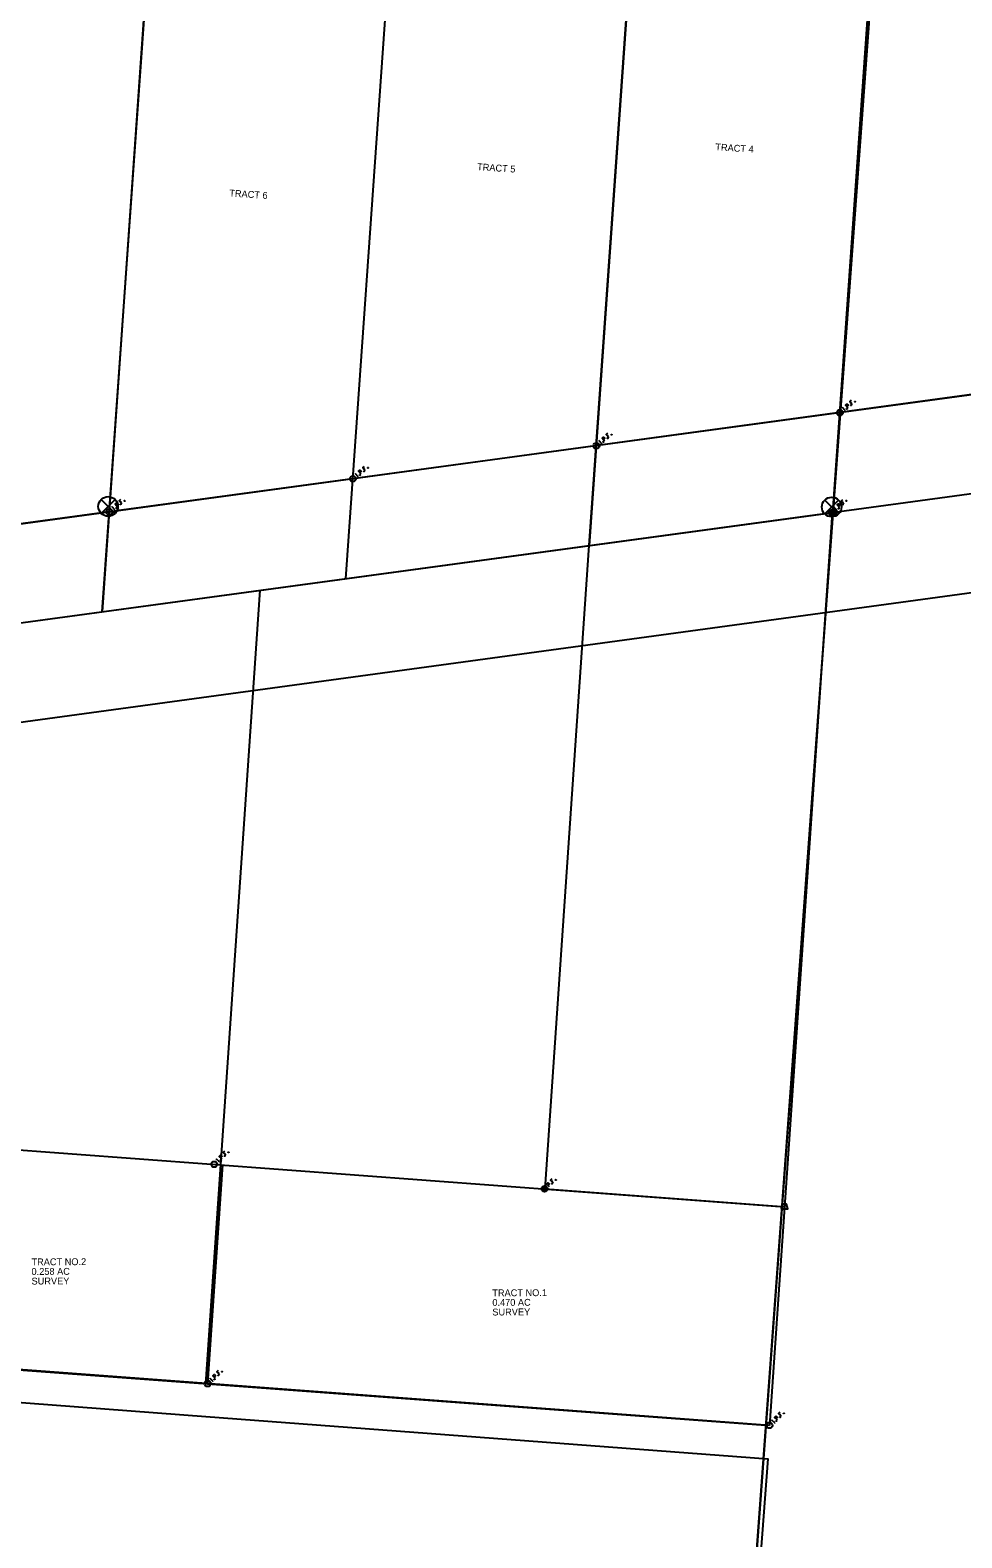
# Model space of a CAD drawing. Extents: x 1532954 to 1577849, y 698998 to 706606.
# Drawn here: x 1574206 to 1574585, y 702823 to 703437 of the extents above; entities that cross this region are included whole.
import ezdxf

# ---------------------------------------------------------------- set-up
doc = ezdxf.new("R2010")
doc.units = 0
for name, color, linetype in [('Default', 7, 'Continuous'), ('DV_X_Property_Line', 7, 'Continuous'), ('GM_X_Major_Lake_Text', 7, 'Continuous'), ('RW_X_Esmt_SH', 7, 'Continuous'), ('SC_Scratch1', 7, 'Continuous'), ('SC_Scratch10', 7, 'Continuous'), ('SC_Scratch3', 7, 'Continuous')]:
    doc.layers.add(name, color=color, linetype=linetype)

msp = doc.modelspace()

# ---------------------------------------------------------------- linework, layer by layer
at = {"layer": 'Default'}
for p, q in [((1574235.11, 703245.67), (1574240.77, 703240.01)), ((1574235.11, 703240.01), (1574240.77, 703245.67)), ((1574237.94, 703242.84), (1574237.94, 703242.84)), ((1574529.51, 703245.46), (1574535.17, 703239.8)), ((1574529.51, 703239.8), (1574535.17, 703245.46)), ((1574532.34, 703242.63), (1574532.34, 703242.63))]:
    msp.add_line(p, q, dxfattribs=at)
for centre in [(1574237.94, 703242.84), (1574532.34, 703242.63)]:
    msp.add_circle(centre, 4, dxfattribs=at)
at = {"layer": 'DV_X_Property_Line'}
for p, q in [((1574433.73, 703226.99), (1574485.27, 703963.13)), ((1574235.57, 703199.97), (1574287.2, 703937.42)), ((1574415.71, 702964.97), (1574433.63, 703226.97)), ((1574277.71, 702885.59), (1574299.81, 703208.73)), ((1574415.71, 702964.97), (1574511.92, 702957.84)), ((1574152.51, 702894.98), (1574505.39, 702868.85))]:
    msp.add_line(p, q, dxfattribs=at)
at = {"layer": 'GM_X_Major_Lake_Text'}
msp.add_line((1574284.68, 699857.31), (1574764.71, 706396.92), dxfattribs=at)
at = {"layer": 'RW_X_Esmt_SH'}
for p, q in [((1574050.43, 703215.11), (1574859.76, 703325.41)), ((1571959, 702849.32), (1574870.56, 703246.15))]:
    msp.add_line(p, q, dxfattribs=at)
at = {"layer": 'SC_Scratch1'}
msp.add_lwpolyline([(1573381.77, 703087.06), (1573407.03, 703090.53), (1573503.76, 703103.79), (1573600.48, 703117.05), (1573696.98, 703130.28), (1573793.21, 703143.47), (1573818.48, 703146.94), (1573843.76, 703150.4), (1573940.5, 703163.67), (1574012.63, 703173.56), (1574009.55, 703132.76), (1573992.57, 702907.55), (1573992.57, 702907.55), (1574153.57, 702895.41), (1574152.55, 702881.84), (1574277.72, 702872.4), (1574506.31, 702855.16), (1574480.3, 702510.33), (1574373.41, 701092.97)], dxfattribs=at)
at = {"layer": 'SC_Scratch10'}
for p, q in [((1571190.11, 702825.26), (1574958.12, 703338.82)), ((1571190.11, 702825.26), (1574958.12, 703338.82)), ((1571190.11, 702825.26), (1574958.12, 703338.82)), ((1571195.51, 702785.63), (1574963.52, 703299.19)), ((1571200.91, 702745.99), (1574968.92, 703259.55))]:
    msp.add_line(p, q, dxfattribs=at)
at = {"layer": 'SC_Scratch3'}
for p, q in [((1574532.83, 703240.28), (1574584.89, 703979.3)), ((1574433.74, 703226.81), (1574485.8, 703965.84)), ((1574334.65, 703213.35), (1574386.71, 703952.38)), ((1574235.56, 703199.89), (1574287.62, 703938.91)), ((1574832.97, 703321.42), (1574040.25, 703213.72)), ((1574830.1, 703280.66), (1574037.38, 703172.96)), ((1574533.04, 703241.39), (1574533.02, 703240.79)), ((1574533, 703240.3), (1572963.42, 703027.05)), ((1574532.5, 703240.23), (1574172.81, 703191.36)), ((1574325.4, 700421.81), (1574533, 703240.3)), ((1574532.5, 703240.23), (1574507.06, 702868.72)), ((1574159.05, 702984.08), (1574513.15, 702957.75)), ((1574278.46, 702885.72), (1574284.56, 702974.75)), ((1574513.15, 702958.85), (1574513.15, 702958.25)), ((1574507.06, 702868.72), (1574153.25, 702895.02))]:
    msp.add_line(p, q, dxfattribs=at)
for points in [[(1574539.05, 703282.91), (1574538, 703284.11), (1574538.39, 703284.46), (1574538.44, 703284.49), (1574538.52, 703284.52), (1574538.56, 703284.52), (1574538.6, 703284.52), (1574538.68, 703284.51), (1574538.74, 703284.48), (1574538.83, 703284.42), (1574538.93, 703284.3), (1574538.95, 703284.26), (1574538.98, 703284.19), (1574539.01, 703284.09), (1574539, 703284.04), (1574538.99, 703283.99), (1574538.97, 703283.94), (1574538.91, 703283.87), (1574538.51, 703283.52)], [(1574540.26, 703286.09), (1574539.69, 703285.59), (1574540.74, 703284.39)], [(1574540.15, 703284.15), (1574540.19, 703284.19), (1574540.23, 703284.19), (1574540.29, 703284.17), (1574540.33, 703284.13), (1574540.34, 703284.07), (1574540.33, 703284.03), (1574540.29, 703283.99), (1574540.24, 703283.99), (1574540.19, 703284), (1574540.15, 703284.05), (1574540.14, 703284.11), (1574540.15, 703284.15)], [(1574540.2, 703285.01), (1574540.61, 703285.36)], [(1574541.76, 703285.57), (1574541.8, 703285.6), (1574541.84, 703285.61), (1574541.9, 703285.59), (1574541.94, 703285.54), (1574541.95, 703285.48), (1574541.94, 703285.44), (1574541.9, 703285.41), (1574541.86, 703285.4), (1574541.8, 703285.42), (1574541.76, 703285.47), (1574541.75, 703285.53), (1574541.76, 703285.57)], [(1574536.69, 703282.96), (1574536.95, 703283.19)], [(1574537.87, 703281.88), (1574536.82, 703283.08)], [(1574537.74, 703281.76), (1574538.01, 703281.99)], [(1574538.45, 703282.67), (1574538.5, 703282.7), (1574538.54, 703282.71), (1574538.6, 703282.69), (1574538.64, 703282.64), (1574538.65, 703282.58), (1574538.64, 703282.54), (1574538.6, 703282.51), (1574538.55, 703282.5), (1574538.5, 703282.52), (1574538.45, 703282.57), (1574538.45, 703282.63), (1574538.45, 703282.67)], [(1574441.17, 703272.63), (1574440.6, 703272.13), (1574441.65, 703270.93)], [(1574441.11, 703271.54), (1574441.52, 703271.9)], [(1574442.67, 703272.1), (1574442.71, 703272.14), (1574442.75, 703272.14), (1574442.81, 703272.13), (1574442.85, 703272.08), (1574442.86, 703272.02), (1574442.85, 703271.98), (1574442.81, 703271.94), (1574442.77, 703271.94), (1574442.71, 703271.96), (1574442.67, 703272), (1574442.66, 703272.06), (1574442.67, 703272.1)], [(1574437.6, 703269.5), (1574437.86, 703269.73)], [(1574438.78, 703268.41), (1574437.73, 703269.62)], [(1574438.65, 703268.3), (1574438.92, 703268.53)], [(1574439.96, 703269.44), (1574438.91, 703270.65), (1574439.3, 703271), (1574439.35, 703271.02), (1574439.43, 703271.05), (1574439.47, 703271.06), (1574439.51, 703271.06), (1574439.59, 703271.04), (1574439.65, 703271.02), (1574439.74, 703270.96), (1574439.84, 703270.84), (1574439.86, 703270.8), (1574439.89, 703270.73), (1574439.92, 703270.63), (1574439.91, 703270.57), (1574439.9, 703270.53), (1574439.88, 703270.48), (1574439.82, 703270.41), (1574439.42, 703270.06)], [(1574439.36, 703269.21), (1574439.41, 703269.24), (1574439.45, 703269.24), (1574439.51, 703269.23), (1574439.55, 703269.18), (1574439.56, 703269.12), (1574439.55, 703269.08), (1574439.51, 703269.04), (1574439.46, 703269.04), (1574439.41, 703269.06), (1574439.36, 703269.11), (1574439.36, 703269.16), (1574439.36, 703269.21)], [(1574441.06, 703270.69), (1574441.1, 703270.72), (1574441.14, 703270.73), (1574441.2, 703270.71), (1574441.24, 703270.66), (1574441.25, 703270.6), (1574441.24, 703270.56), (1574441.2, 703270.53), (1574441.16, 703270.52), (1574441.1, 703270.54), (1574441.06, 703270.59), (1574441.05, 703270.65), (1574441.06, 703270.69)], [(1574338.51, 703256.04), (1574338.77, 703256.27)], [(1574339.7, 703254.95), (1574338.64, 703256.15)], [(1574339.56, 703254.83), (1574339.83, 703255.07)], [(1574340.87, 703255.98), (1574339.82, 703257.18), (1574340.22, 703257.53), (1574340.27, 703257.56), (1574340.34, 703257.59), (1574340.38, 703257.59), (1574340.42, 703257.6), (1574340.5, 703257.58), (1574340.56, 703257.55), (1574340.65, 703257.49), (1574340.75, 703257.38), (1574340.77, 703257.33), (1574340.8, 703257.26), (1574340.83, 703257.17), (1574340.82, 703257.11), (1574340.81, 703257.07), (1574340.79, 703257.01), (1574340.73, 703256.95), (1574340.33, 703256.6)], [(1574340.27, 703255.74), (1574340.32, 703255.78), (1574340.36, 703255.78), (1574340.42, 703255.77), (1574340.46, 703255.72), (1574340.47, 703255.66), (1574340.46, 703255.62), (1574340.42, 703255.58), (1574340.37, 703255.58), (1574340.32, 703255.59), (1574340.27, 703255.64), (1574340.27, 703255.7), (1574340.27, 703255.74)], [(1574342.08, 703259.17), (1574341.51, 703258.67), (1574342.56, 703257.46)], [(1574341.97, 703257.22), (1574342.01, 703257.26), (1574342.05, 703257.26), (1574342.11, 703257.25), (1574342.15, 703257.2), (1574342.16, 703257.14), (1574342.15, 703257.1), (1574342.11, 703257.06), (1574342.07, 703257.06), (1574342.01, 703257.08), (1574341.97, 703257.12), (1574341.96, 703257.18), (1574341.97, 703257.22)], [(1574342.02, 703258.08), (1574342.43, 703258.44)], [(1574343.58, 703258.64), (1574343.62, 703258.68), (1574343.67, 703258.68), (1574343.72, 703258.66), (1574343.76, 703258.62), (1574343.77, 703258.56), (1574343.76, 703258.52), (1574343.72, 703258.48), (1574343.68, 703258.48), (1574343.62, 703258.49), (1574343.58, 703258.54), (1574343.57, 703258.6), (1574343.58, 703258.64)], [(1574239.42, 703242.57), (1574239.68, 703242.81)], [(1574240.61, 703241.49), (1574239.55, 703242.69)], [(1574240.47, 703241.37), (1574240.74, 703241.6)], [(1574241.78, 703242.52), (1574240.73, 703243.72), (1574241.13, 703244.07), (1574241.18, 703244.1), (1574241.25, 703244.13), (1574241.29, 703244.13), (1574241.33, 703244.13), (1574241.41, 703244.12), (1574241.47, 703244.09), (1574241.56, 703244.03), (1574241.66, 703243.92), (1574241.68, 703243.87), (1574241.71, 703243.8), (1574241.74, 703243.7), (1574241.73, 703243.65), (1574241.72, 703243.61), (1574241.7, 703243.55), (1574241.64, 703243.48), (1574241.24, 703243.13)], [(1574241.19, 703242.28), (1574241.23, 703242.32), (1574241.27, 703242.32), (1574241.33, 703242.3), (1574241.37, 703242.26), (1574241.38, 703242.2), (1574241.37, 703242.15), (1574241.33, 703242.12), (1574241.29, 703242.12), (1574241.23, 703242.13), (1574241.19, 703242.18), (1574241.18, 703242.24), (1574241.19, 703242.28)], [(1574242.99, 703245.7), (1574242.42, 703245.2), (1574243.47, 703244)], [(1574242.88, 703243.76), (1574242.92, 703243.8), (1574242.96, 703243.8), (1574243.02, 703243.78), (1574243.06, 703243.74), (1574243.07, 703243.68), (1574243.06, 703243.64), (1574243.02, 703243.6), (1574242.98, 703243.6), (1574242.92, 703243.61), (1574242.88, 703243.66), (1574242.87, 703243.72), (1574242.88, 703243.76)], [(1574242.93, 703244.62), (1574243.34, 703244.97)], [(1574244.49, 703245.18), (1574244.53, 703245.22), (1574244.58, 703245.22), (1574244.63, 703245.2), (1574244.68, 703245.15), (1574244.68, 703245.09), (1574244.68, 703245.05), (1574244.63, 703245.02), (1574244.59, 703245.01), (1574244.53, 703245.03), (1574244.49, 703245.08), (1574244.48, 703245.14), (1574244.49, 703245.18)], [(1574533.35, 703242.22), (1574533.6, 703242.48)], [(1574534.61, 703241.22), (1574533.48, 703242.35)], [(1574534.49, 703241.1), (1574534.74, 703241.35)], [(1574535.72, 703242.34), (1574534.58, 703243.46), (1574534.95, 703243.84), (1574535, 703243.87), (1574535.07, 703243.9), (1574535.11, 703243.91), (1574535.15, 703243.92), (1574535.23, 703243.9), (1574535.3, 703243.88), (1574535.38, 703243.83), (1574535.49, 703243.72), (1574535.52, 703243.68), (1574535.56, 703243.61), (1574535.59, 703243.51), (1574535.59, 703243.46), (1574535.58, 703243.42), (1574535.56, 703243.36), (1574535.51, 703243.29), (1574535.13, 703242.91)], [(1574535.14, 703242.06), (1574535.18, 703242.09), (1574535.22, 703242.1), (1574535.28, 703242.09), (1574535.32, 703242.04), (1574535.33, 703241.99), (1574535.33, 703241.94), (1574535.29, 703241.9), (1574535.25, 703241.9), (1574535.19, 703241.91), (1574535.14, 703241.96), (1574535.13, 703242.01), (1574535.14, 703242.06)], [(1574536.7, 703245.6), (1574536.16, 703245.06), (1574537.3, 703243.93)], [(1574536.72, 703243.65), (1574536.76, 703243.69), (1574536.8, 703243.7), (1574536.86, 703243.69), (1574536.9, 703243.64), (1574536.92, 703243.58), (1574536.91, 703243.54), (1574536.87, 703243.5), (1574536.83, 703243.5), (1574536.77, 703243.51), (1574536.73, 703243.55), (1574536.71, 703243.61), (1574536.72, 703243.65)], [(1574536.72, 703244.51), (1574537.1, 703244.89)], [(1574538.23, 703245.18), (1574538.27, 703245.22), (1574538.31, 703245.22), (1574538.37, 703245.21), (1574538.42, 703245.17), (1574538.43, 703245.11), (1574538.42, 703245.07), (1574538.38, 703245.03), (1574538.34, 703245.02), (1574538.28, 703245.03), (1574538.24, 703245.08), (1574538.23, 703245.14), (1574538.23, 703245.18)], [(1574281.92, 702977), (1574282.16, 702977.25)], [(1574283.18, 702976), (1574282.04, 702977.13)], [(1574284.28, 702977.11), (1574283.14, 702978.24), (1574283.51, 702978.61), (1574283.56, 702978.64), (1574283.63, 702978.68), (1574283.68, 702978.69), (1574283.72, 702978.69), (1574283.79, 702978.68), (1574283.86, 702978.66), (1574283.95, 702978.6), (1574284.05, 702978.5), (1574284.08, 702978.45), (1574284.12, 702978.38), (1574284.15, 702978.29), (1574284.15, 702978.23), (1574284.14, 702978.19), (1574284.12, 702978.13), (1574284.07, 702978.06), (1574283.7, 702977.69)], [(1574285.26, 702980.37), (1574284.72, 702979.83), (1574285.86, 702978.71)], [(1574285.28, 702979.28), (1574285.66, 702979.67)], [(1574285.28, 702978.43), (1574285.32, 702978.47), (1574285.36, 702978.47), (1574285.42, 702978.46), (1574285.47, 702978.42), (1574285.48, 702978.36), (1574285.47, 702978.32), (1574285.43, 702978.28), (1574285.39, 702978.27), (1574285.33, 702978.28), (1574285.29, 702978.33), (1574285.28, 702978.39), (1574285.28, 702978.43)], [(1574286.8, 702979.95), (1574286.83, 702979.99), (1574286.88, 702980), (1574286.93, 702979.99), (1574286.98, 702979.94), (1574286.99, 702979.88), (1574286.99, 702979.84), (1574286.95, 702979.8), (1574286.91, 702979.8), (1574286.85, 702979.81), (1574286.8, 702979.85), (1574286.79, 702979.91), (1574286.8, 702979.95)], [(1574283.05, 702975.87), (1574283.3, 702976.12)], [(1574283.7, 702976.83), (1574283.74, 702976.87), (1574283.78, 702976.88), (1574283.84, 702976.86), (1574283.88, 702976.82), (1574283.9, 702976.76), (1574283.89, 702976.72), (1574283.85, 702976.68), (1574283.81, 702976.67), (1574283.75, 702976.69), (1574283.71, 702976.73), (1574283.69, 702976.79), (1574283.7, 702976.83)], [(1574417.47, 702965.87), (1574416.33, 702966.99), (1574416.7, 702967.37), (1574416.75, 702967.4), (1574416.82, 702967.44), (1574416.87, 702967.44), (1574416.91, 702967.45), (1574416.98, 702967.44), (1574417.05, 702967.42), (1574417.14, 702967.36), (1574417.25, 702967.25), (1574417.27, 702967.21), (1574417.31, 702967.14), (1574417.34, 702967.05), (1574417.34, 702966.99), (1574417.33, 702966.95), (1574417.31, 702966.89), (1574417.26, 702966.82), (1574416.89, 702966.44)], [(1574418.45, 702969.13), (1574417.92, 702968.59), (1574419.05, 702967.47)], [(1574418.47, 702968.04), (1574418.85, 702968.43)], [(1574418.47, 702967.19), (1574418.51, 702967.22), (1574418.55, 702967.23), (1574418.61, 702967.22), (1574418.66, 702967.17), (1574418.67, 702967.11), (1574418.66, 702967.07), (1574418.63, 702967.03), (1574418.58, 702967.03), (1574418.52, 702967.04), (1574418.48, 702967.09), (1574418.47, 702967.14), (1574418.47, 702967.19)], [(1574419.99, 702968.71), (1574420.02, 702968.75), (1574420.07, 702968.76), (1574420.13, 702968.74), (1574420.17, 702968.7), (1574420.18, 702968.64), (1574420.18, 702968.6), (1574420.14, 702968.56), (1574420.1, 702968.56), (1574420.04, 702968.57), (1574419.99, 702968.61), (1574419.98, 702968.67), (1574419.99, 702968.71)], [(1574282.65, 702891.08), (1574282.12, 702890.54), (1574283.25, 702889.42)], [(1574279.31, 702887.71), (1574279.56, 702887.96)], [(1574280.57, 702886.71), (1574279.43, 702887.83)], [(1574280.44, 702886.58), (1574280.69, 702886.83)], [(1574281.67, 702887.82), (1574280.53, 702888.95), (1574280.91, 702889.32), (1574280.95, 702889.35), (1574281.03, 702889.39), (1574281.07, 702889.4), (1574281.11, 702889.4), (1574281.18, 702889.39), (1574281.25, 702889.37), (1574281.34, 702889.31), (1574281.45, 702889.21), (1574281.48, 702889.16), (1574281.51, 702889.09), (1574281.54, 702889), (1574281.54, 702888.94), (1574281.54, 702888.9), (1574281.51, 702888.84), (1574281.46, 702888.77), (1574281.09, 702888.4)], [(1574281.09, 702887.54), (1574281.13, 702887.58), (1574281.17, 702887.59), (1574281.23, 702887.57), (1574281.28, 702887.53), (1574281.29, 702887.47), (1574281.28, 702887.43), (1574281.24, 702887.39), (1574281.2, 702887.38), (1574281.14, 702887.4), (1574281.1, 702887.44), (1574281.09, 702887.5), (1574281.09, 702887.54)], [(1574282.67, 702889.99), (1574283.05, 702890.38)], [(1574282.67, 702889.14), (1574282.71, 702889.18), (1574282.75, 702889.18), (1574282.81, 702889.17), (1574282.86, 702889.13), (1574282.87, 702889.07), (1574282.87, 702889.03), (1574282.83, 702888.99), (1574282.79, 702888.98), (1574282.73, 702888.99), (1574282.68, 702889.04), (1574282.67, 702889.1), (1574282.67, 702889.14)], [(1574284.19, 702890.66), (1574284.23, 702890.7), (1574284.27, 702890.71), (1574284.33, 702890.7), (1574284.37, 702890.65), (1574284.38, 702890.59), (1574284.38, 702890.55), (1574284.34, 702890.51), (1574284.3, 702890.51), (1574284.24, 702890.52), (1574284.19, 702890.56), (1574284.18, 702890.62), (1574284.19, 702890.66)], [(1574511.25, 702874.09), (1574510.72, 702873.55), (1574511.85, 702872.42)], [(1574511.27, 702873), (1574511.65, 702873.38)], [(1574512.79, 702873.67), (1574512.83, 702873.71), (1574512.87, 702873.71), (1574512.93, 702873.7), (1574512.97, 702873.66), (1574512.98, 702873.6), (1574512.98, 702873.56), (1574512.94, 702873.52), (1574512.9, 702873.51), (1574512.84, 702873.52), (1574512.79, 702873.57), (1574512.78, 702873.63), (1574512.79, 702873.67)], [(1574507.91, 702870.72), (1574508.16, 702870.97)], [(1574509.17, 702869.71), (1574508.03, 702870.84)], [(1574509.04, 702869.59), (1574509.29, 702869.84)], [(1574510.27, 702870.83), (1574509.13, 702871.95), (1574509.51, 702872.33), (1574509.55, 702872.36), (1574509.63, 702872.4), (1574509.67, 702872.4), (1574509.71, 702872.41), (1574509.78, 702872.39), (1574509.85, 702872.37), (1574509.94, 702872.32), (1574510.05, 702872.21), (1574510.07, 702872.17), (1574510.11, 702872.1), (1574510.14, 702872.01), (1574510.14, 702871.95), (1574510.13, 702871.91), (1574510.11, 702871.85), (1574510.06, 702871.78), (1574509.69, 702871.4)], [(1574509.69, 702870.55), (1574509.73, 702870.59), (1574509.77, 702870.59), (1574509.83, 702870.58), (1574509.87, 702870.53), (1574509.89, 702870.48), (1574509.88, 702870.43), (1574509.84, 702870.4), (1574509.8, 702870.39), (1574509.74, 702870.4), (1574509.7, 702870.45), (1574509.69, 702870.5), (1574509.69, 702870.55)], [(1574511.27, 702872.14), (1574511.31, 702872.18), (1574511.35, 702872.19), (1574511.41, 702872.18), (1574511.46, 702872.13), (1574511.47, 702872.07), (1574511.46, 702872.03), (1574511.43, 702871.99), (1574511.38, 702871.99), (1574511.33, 702872), (1574511.28, 702872.04), (1574511.27, 702872.1), (1574511.27, 702872.14)]]:
    msp.add_lwpolyline(points, dxfattribs=at)
for points in [[(1574531.57, 703239.44), (1574534.37, 703239.34), (1574533.84, 703241.36), (1574532.24, 703241.42)], [(1574511.76, 702956.84), (1574514.56, 702956.85), (1574513.95, 702958.85), (1574512.35, 702958.84)]]:
    msp.add_lwpolyline(points, close=True, dxfattribs=at)
for centre, radius in [((1574535.7, 703281.03), 1.2), ((1574436.61, 703267.57), 1.2), ((1574337.52, 703254.11), 1.2), ((1574238.43, 703240.64), 1.2), ((1574532.5, 703240.23), 1.2), ((1574281.07, 702975.01), 1.2), ((1574415.49, 702965.01), 1.2), ((1574415.49, 702965.01), 0.495), ((1574278.46, 702885.72), 1.2), ((1574507.06, 702868.72), 1.2)]:
    msp.add_circle(centre, radius, dxfattribs=at)

# ---------------------------------------------------------------- texts
for s, rotation, p in [('TRACT 4', 356.23722, (1574484.94, 703387.87)), ('TRACT 5', 356.23722, (1574387.99, 703379.79)), ('TRACT 6', 356.23722, (1574287.16, 703369.07)), ('TRACT NO.2', 0.24841, (1574206.74, 702933.87)), ('0.258 AC', 0.24841, (1574206.76, 702929.97)), ('SURVEY', 0.24841, (1574206.77, 702926.06)), ('TRACT NO.1', 0.24841, (1574394.25, 702921.26)), ('0.470 AC', 0.24841, (1574394.27, 702917.36)), ('SURVEY', 0.24841, (1574394.28, 702913.46))]:
    msp.add_text(s, height=2.8, rotation=rotation, dxfattribs=at).set_placement(p)

doc.saveas('drawing.dxf')
